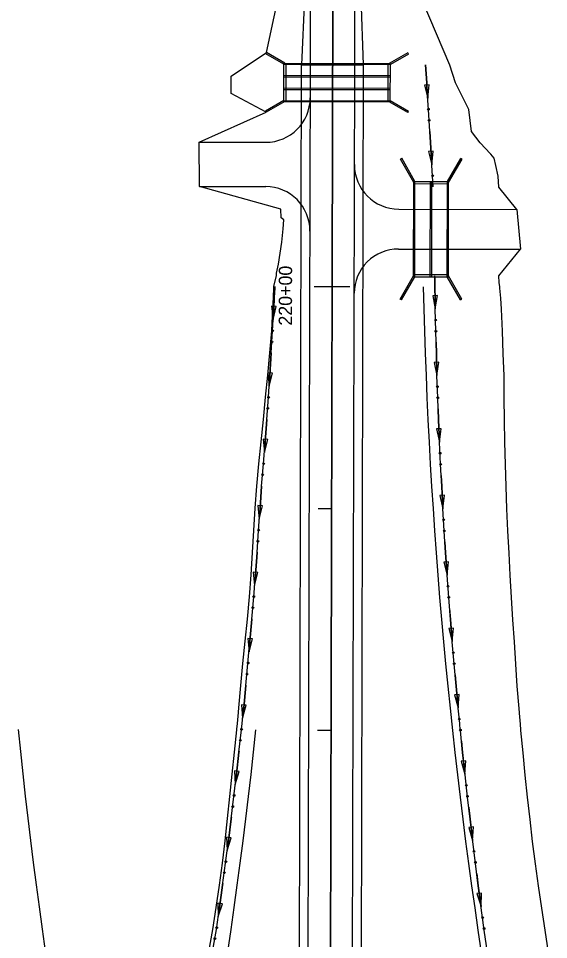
# Model space of a CAD drawing. Extents: x 1611108 to 1749517, y 619561 to 797725.
# Drawn here: x 1717474.1 to 1717713.2, y 766943.6 to 767358.9 of the extents above; entities that cross this region are included whole.
import ezdxf

# ---------------------------------------------------------------- set-up
doc = ezdxf.new("R2010")
doc.units = 0
for name, color, linetype in [('Level 8', 7, 'Continuous'), ('R_Ditch', 7, 'Continuous'), ('R_Drainage', 7, 'Continuous'), ('R_Horz Alg', 7, 'Continuous'), ('R_Horz Alg Stationing_Side Road', 7, 'Continuous'), ('R_Proposed Const Limits', 7, 'Continuous'), ('R_Proposed Road', 7, 'Continuous')]:
    doc.layers.add(name, color=color, linetype=linetype)

msp = doc.modelspace()

# ---------------------------------------------------------------- linework, layer by layer
at = {"layer": 'Level 8'}
msp.add_line((1717616.46, 767638.01), (1717610.87, 765238.01), dxfattribs=at)
at = {"layer": 'R_Ditch'}
for p, q in [((1717659.35, 767328.99), (1717657.24, 767328.86)), ((1717657.24, 767328.86), (1717658.67, 767322.94)), ((1717658.67, 767322.94), (1717659.35, 767328.99)), ((1717661.22, 767299.01), (1717659.11, 767298.88)), ((1717660.54, 767292.96), (1717661.22, 767299.01)), ((1717659.11, 767298.88), (1717660.54, 767292.96)), ((1717663.07, 767233.92), (1717660.95, 767233.88)), ((1717660.95, 767233.88), (1717662.12, 767227.9)), ((1717662.12, 767227.9), (1717663.07, 767233.92)), ((1717590.37, 767229.02), (1717588.26, 767229.13)), ((1717588.26, 767229.13), (1717589, 767223.09)), ((1717589, 767223.09), (1717590.37, 767229.02)), ((1717663.75, 767203.9), (1717661.64, 767203.84)), ((1717661.64, 767203.84), (1717662.87, 767197.87)), ((1717662.87, 767197.87), (1717663.75, 767203.9)), ((1717588.66, 767199.02), (1717586.55, 767199.16)), ((1717586.55, 767199.16), (1717587.21, 767193.1)), ((1717587.21, 767193.1), (1717588.66, 767199.02)), ((1717664.81, 767173.9), (1717662.7, 767173.81)), ((1717662.7, 767173.81), (1717664.01, 767167.86)), ((1717664.01, 767167.86), (1717664.81, 767173.9)), ((1717586.57, 767169.04), (1717584.46, 767169.21)), ((1717584.46, 767169.21), (1717585.05, 767163.14)), ((1717585.05, 767163.14), (1717586.57, 767169.04)), ((1717666.26, 767143.91), (1717664.15, 767143.79)), ((1717664.15, 767143.79), (1717665.54, 767137.86)), ((1717665.54, 767137.86), (1717666.26, 767143.91)), ((1717584.2, 767139.11), (1717582.09, 767139.25)), ((1717582.09, 767139.25), (1717582.76, 767133.19)), ((1717582.76, 767133.19), (1717584.2, 767139.11)), ((1717668.1, 767113.94), (1717665.99, 767113.8)), ((1717665.99, 767113.8), (1717667.45, 767107.88)), ((1717667.45, 767107.88), (1717668.1, 767113.94)), ((1717582.14, 767109.13), (1717580.03, 767109.29)), ((1717580.03, 767109.29), (1717580.62, 767103.23)), ((1717580.62, 767103.23), (1717582.14, 767109.13)), ((1717670.32, 767084), (1717668.21, 767083.83)), ((1717668.21, 767083.83), (1717669.75, 767077.93)), ((1717669.75, 767077.93), (1717670.32, 767084)), ((1717579.7, 767079.18), (1717577.59, 767079.37)), ((1717577.59, 767079.37), (1717578.11, 767073.3)), ((1717578.11, 767073.3), (1717579.7, 767079.18)), ((1717672.92, 767054.09), (1717670.82, 767053.89)), ((1717670.82, 767053.89), (1717672.43, 767048.01)), ((1717672.43, 767048.01), (1717672.92, 767054.09)), ((1717576.88, 767049.26), (1717574.77, 767049.48)), ((1717574.77, 767049.48), (1717575.21, 767043.4)), ((1717575.21, 767043.4), (1717576.88, 767049.26)), ((1717675.91, 767024.21), (1717673.8, 767023.99)), ((1717673.8, 767023.99), (1717675.49, 767018.13)), ((1717675.49, 767018.13), (1717675.91, 767024.21)), ((1717573.67, 767019.38), (1717571.57, 767019.63)), ((1717571.57, 767019.63), (1717571.93, 767013.54)), ((1717571.93, 767013.54), (1717573.67, 767019.38)), ((1717679.27, 766994.38), (1717677.17, 766994.12)), ((1717677.17, 766994.12), (1717678.93, 766988.29)), ((1717678.93, 766988.29), (1717679.27, 766994.38)), ((1717570.09, 766989.54), (1717567.99, 766989.82)), ((1717567.99, 766989.82), (1717568.27, 766983.73)), ((1717568.27, 766983.73), (1717570.09, 766989.54)), ((1717683.01, 766964.59), (1717680.91, 766964.31)), ((1717680.91, 766964.31), (1717682.75, 766958.5)), ((1717682.75, 766958.5), (1717683.01, 766964.59)), ((1717566.13, 766959.75), (1717564.03, 766960.05)), ((1717564.03, 766960.05), (1717564.23, 766953.96)), ((1717564.23, 766953.96), (1717566.13, 766959.75))]:
    msp.add_line(p, q, dxfattribs=at)
for points in [[(1717661.17, 767282.9), (1717660.85, 767287.9), (1717660.56, 767292.58), (1717660.36, 767295.9), (1717660.24, 767297.78), (1717660.23, 767297.9), (1717659.92, 767302.9), (1717659.61, 767307.91), (1717658.98, 767317.91), (1717658.36, 767327.91), (1717658.23, 767329.91), (1717657.73, 767337.91)], [(1717657.73, 767337.91), (1717658.23, 767329.91), (1717658.36, 767327.91), (1717658.67, 767322.94)], [(1717659.6, 767307.97), (1717659.6, 767307.93)], [(1717659.6, 767307.93), (1717659.61, 767307.91), (1717659.92, 767302.9), (1717660.23, 767297.9), (1717660.24, 767297.78), (1717660.36, 767295.9), (1717660.54, 767292.96)], [(1717685.62, 766937.84), (1717684.21, 766947.85), (1717682.84, 766957.85), (1717681.51, 766967.85), (1717680.23, 766977.86), (1717678.99, 766987.86), (1717677.79, 766997.86), (1717676.63, 767007.87), (1717675.52, 767017.87), (1717674.45, 767027.87), (1717673.43, 767037.87), (1717673.38, 767038.32), (1717673.15, 767040.69), (1717672.96, 767042.61), (1717672.83, 767043.88), (1717672.44, 767047.88), (1717672.44, 767047.91), (1717671.5, 767057.88), (1717670.61, 767067.88), (1717669.75, 767077.88), (1717668.94, 767087.88), (1717668.18, 767097.89), (1717667.45, 767107.89), (1717666.77, 767117.89), (1717666.13, 767127.89), (1717665.54, 767137.89), (1717664.99, 767147.89), (1717664.48, 767157.89), (1717664.01, 767167.9), (1717663.59, 767177.9), (1717663.21, 767187.9), (1717662.87, 767197.9), (1717662.58, 767207.9), (1717662.33, 767217.9), (1717662.12, 767227.9), (1717662.03, 767232.84), (1717661.96, 767237.3), (1717661.95, 767237.9), (1717661.92, 767239.94), (1717661.89, 767242.9)], [(1717661.89, 767242.4), (1717661.92, 767239.94), (1717661.95, 767237.9), (1717661.96, 767237.3), (1717662.03, 767232.84), (1717662.12, 767227.9)], [(1717561.58, 766938.13), (1717563.4, 766948.13), (1717564.83, 766958.13), (1717566.21, 766968.12), (1717567.54, 766978.12), (1717568.84, 766988.12), (1717570.09, 766998.11), (1717571.29, 767008.11), (1717572.46, 767018.11), (1717573.58, 767028.11), (1717574.66, 767038.1), (1717574.71, 767038.55), (1717574.95, 767040.92), (1717575.15, 767042.84), (1717575.29, 767044.11), (1717575.69, 767048.1), (1717575.7, 767048.13), (1717576.69, 767058.1), (1717577.63, 767068.1), (1717578.54, 767078.09), (1717579.4, 767088.09), (1717580.22, 767098.09), (1717581, 767108.09), (1717581.74, 767118.09), (1717582.43, 767128.08), (1717583.07, 767138.08), (1717583.81, 767148.08), (1717584.65, 767158.08), (1717585.43, 767168.08), (1717586.18, 767178.08), (1717586.88, 767188.07), (1717587.54, 767198.07), (1717588.16, 767208.07), (1717588.73, 767218.07), (1717589.26, 767228.07), (1717589.51, 767233.01), (1717589.72, 767237.47), (1717589.75, 767238.07)], [(1717589.75, 767238.07), (1717589.72, 767237.47), (1717589.51, 767233.01), (1717589.26, 767228.07), (1717589, 767223.09)], [(1717683.01, 766937.85), (1717681.51, 766947.85), (1717680.06, 766957.86), (1717678.64, 766967.86), (1717677.28, 766977.86), (1717675.95, 766987.87), (1717674.67, 766997.87), (1717673.43, 767007.87), (1717672.23, 767017.88), (1717671.08, 767027.88), (1717669.97, 767037.88), (1717668.9, 767047.88), (1717667.88, 767057.89), (1717666.9, 767067.89), (1717665.96, 767077.89), (1717665.07, 767087.89), (1717664.21, 767097.89), (1717663.41, 767107.9), (1717662.64, 767117.9), (1717661.92, 767127.9), (1717661.24, 767137.9), (1717660.6, 767147.9), (1717660.01, 767157.9), (1717659.46, 767167.91), (1717658.95, 767177.91), (1717658.49, 767187.91), (1717658.07, 767197.91), (1717657.69, 767207.91), (1717657.35, 767217.91), (1717657.06, 767227.91), (1717656.81, 767237.91)], [(1717662.45, 767212.91), (1717662.45, 767212.87)], [(1717662.45, 767212.87), (1717662.58, 767207.9), (1717662.87, 767197.9), (1717662.87, 767197.87)], [(1717588.16, 767208.07), (1717588.16, 767208.07), (1717587.54, 767198.07), (1717587.21, 767193.1)], [(1717588.16, 767208.11), (1717588.16, 767208.07)], [(1717663.4, 767182.88), (1717663.4, 767182.85)], [(1717663.4, 767182.84), (1717663.59, 767177.9), (1717664.01, 767167.9), (1717664.01, 767167.86)], [(1717586.18, 767178.1), (1717586.18, 767178.08), (1717585.43, 767168.08), (1717585.05, 767163.14)], [(1717586.18, 767178.14), (1717586.18, 767178.1)], [(1717664.73, 767152.87), (1717664.73, 767152.84)], [(1717664.73, 767152.84), (1717664.99, 767147.89), (1717665.54, 767137.89), (1717665.54, 767137.86)], [(1717583.82, 767148.15), (1717583.81, 767148.08), (1717583.07, 767138.08), (1717582.76, 767133.19)], [(1717583.82, 767148.19), (1717583.82, 767148.16)], [(1717666.45, 767122.89), (1717666.45, 767122.85)], [(1717666.45, 767122.85), (1717666.77, 767117.89), (1717667.45, 767107.89), (1717667.45, 767107.88)], [(1717581.74, 767118.19), (1717581.74, 767118.09), (1717581, 767108.09), (1717580.62, 767103.23)], [(1717581.74, 767118.23), (1717581.74, 767118.19)], [(1717668.56, 767092.92), (1717668.56, 767092.89)], [(1717668.56, 767092.88), (1717668.94, 767087.88), (1717669.75, 767077.93)], [(1717579.42, 767088.24), (1717579.4, 767088.09), (1717578.54, 767078.09), (1717578.11, 767073.3)], [(1717579.42, 767088.28), (1717579.42, 767088.24)], [(1717671.05, 767062.99), (1717671.05, 767062.95)], [(1717671.05, 767062.95), (1717671.5, 767057.88), (1717672.43, 767048.01)], [(1717576.71, 767058.33), (1717576.69, 767058.1), (1717575.7, 767048.13), (1717575.69, 767048.1), (1717575.29, 767044.11), (1717575.21, 767043.4)], [(1717576.71, 767058.36), (1717576.71, 767058.33)], [(1717486.38, 766938.31), (1717484.96, 766948.31), (1717483.59, 766958.31), (1717482.26, 766968.32), (1717480.96, 766978.32), (1717479.72, 766988.32), (1717478.51, 766998.33), (1717477.35, 767008.33), (1717476.23, 767018.33), (1717475.16, 767028.33), (1717474.13, 767038.34)], [(1717568.53, 766938.12), (1717569.99, 766948.11), (1717571.41, 766958.11), (1717572.79, 766968.11), (1717574.13, 766978.1), (1717575.42, 766988.1), (1717576.67, 766998.1), (1717577.88, 767008.1), (1717579.05, 767018.09), (1717580.17, 767028.09), (1717581.25, 767038.09)], [(1717673.92, 767033.09), (1717673.92, 767033.05)], [(1717673.92, 767033.05), (1717674.45, 767027.87), (1717675.49, 767018.13)], [(1717573.62, 767028.45), (1717573.58, 767028.11), (1717572.46, 767018.11), (1717571.93, 767013.54)], [(1717573.62, 767028.49), (1717573.62, 767028.45)], [(1717677.17, 767003.23), (1717677.17, 767003.19)], [(1717677.17, 767003.19), (1717677.79, 766997.86), (1717678.93, 766988.29)], [(1717570.15, 766998.61), (1717570.09, 766998.11), (1717568.84, 766988.12), (1717568.27, 766983.73)], [(1717570.15, 766998.65), (1717570.15, 766998.61)], [(1717680.8, 766973.41), (1717680.8, 766973.37)], [(1717680.8, 766973.37), (1717681.51, 766967.85), (1717682.75, 766958.5)], [(1717566.3, 766968.82), (1717566.21, 766968.12), (1717564.83, 766958.13), (1717564.23, 766953.96)], [(1717566.3, 766968.86), (1717566.3, 766968.82)], [(1717684.8, 766943.64), (1717684.81, 766943.6)]]:
    msp.add_lwpolyline(points, dxfattribs=at)
for centre in [(1717659.02, 767317.95), (1717659.33, 767312.94), (1717660.89, 767287.97), (1717662.26, 767222.9), (1717588.77, 767218.09), (1717662.36, 767217.89), (1717588.48, 767213.08), (1717663.08, 767192.87), (1717586.92, 767188.1), (1717663.24, 767187.86), (1717586.57, 767183.11), (1717664.28, 767162.86), (1717584.69, 767158.15), (1717664.51, 767157.85), (1717584.27, 767153.16), (1717665.87, 767132.86), (1717582.47, 767128.19), (1717666.17, 767127.86), (1717582.12, 767123.2), (1717667.85, 767102.89), (1717580.27, 767098.24), (1717668.21, 767097.89), (1717579.86, 767093.24), (1717670.21, 767072.95), (1717577.69, 767068.31), (1717670.64, 767067.96), (1717577.22, 767063.32), (1717672.95, 767043.03), (1717574.73, 767038.42), (1717673.45, 767038.05), (1717574.19, 767033.44), (1717676.08, 767013.16), (1717571.38, 767008.57), (1717676.63, 767008.18), (1717570.78, 767003.59), (1717679.58, 766983.33), (1717567.66, 766978.76), (1717680.2, 766978.36), (1717567, 766973.79), (1717683.46, 766953.54), (1717563.56, 766949), (1717684.14, 766948.58), (1717562.7, 766944.07)]:
    msp.add_circle(centre, 0.375, dxfattribs=at)
at = {"layer": 'R_Drainage'}
for p, q in [((1717585.63, 767342.99), (1717585.97, 767343.57)), ((1717593.85, 767338.23), (1717585.63, 767342.99)), ((1717594.32, 767338.72), (1717585.97, 767343.57)), ((1717649.75, 767343.42), (1717641.38, 767338.61)), ((1717650.09, 767342.84), (1717641.85, 767338.11)), ((1717650.09, 767342.84), (1717649.75, 767343.42)), ((1717593.81, 767321.39), (1717593.85, 767338.73)), ((1717593.85, 767338.73), (1717641.85, 767338.61)), ((1717593.85, 767338.23), (1717641.85, 767338.11)), ((1717594.81, 767321.39), (1717594.85, 767338.72)), ((1717640.81, 767321.28), (1717640.85, 767338.62)), ((1717641.81, 767321.28), (1717641.85, 767338.61)), ((1717593.84, 767333.23), (1717641.84, 767333.11)), ((1717593.84, 767332.56), (1717641.84, 767332.45)), ((1717593.82, 767327.56), (1717641.82, 767327.45)), ((1717593.82, 767326.89), (1717641.82, 767326.78)), ((1717593.81, 767321.89), (1717585.57, 767317.16)), ((1717594.28, 767321.39), (1717585.9, 767316.58)), ((1717593.81, 767321.89), (1717641.81, 767321.78)), ((1717593.81, 767321.39), (1717641.81, 767321.28)), ((1717649.69, 767316.43), (1717641.34, 767321.28)), ((1717650.03, 767317.01), (1717641.81, 767321.78)), ((1717585.9, 767316.58), (1717585.57, 767317.16)), ((1717649.69, 767316.43), (1717650.03, 767317.01)), ((1717646.37, 767295.5), (1717646.95, 767295.83)), ((1717652.42, 767284.96), (1717646.37, 767295.5)), ((1717652.92, 767285.42), (1717646.95, 767295.83)), ((1717667.59, 767285.39), (1717673.61, 767295.77)), ((1717668.09, 767284.92), (1717674.19, 767295.43)), ((1717674.19, 767295.43), (1717673.61, 767295.77)), ((1717652.32, 767242.42), (1717652.42, 767285.42)), ((1717652.42, 767285.42), (1717668.09, 767285.39)), ((1717652.42, 767284.42), (1717668.09, 767284.39)), ((1717652.82, 767242.42), (1717652.92, 767285.42)), ((1717659.82, 767242.4), (1717659.92, 767285.4)), ((1717660.49, 767242.4), (1717660.59, 767285.4)), ((1717667.49, 767242.39), (1717667.59, 767285.39)), ((1717667.99, 767242.39), (1717668.09, 767285.39)), ((1717646.22, 767232.38), (1717652.32, 767242.89)), ((1717646.8, 767232.04), (1717652.82, 767242.42)), ((1717652.32, 767243.42), (1717667.99, 767243.39)), ((1717652.32, 767242.42), (1717667.99, 767242.39)), ((1717673.46, 767231.98), (1717667.49, 767242.39)), ((1717674.04, 767232.31), (1717667.99, 767242.85)), ((1717646.8, 767232.04), (1717646.22, 767232.38)), ((1717673.46, 767231.98), (1717674.04, 767232.31))]:
    msp.add_line(p, q, dxfattribs=at)
at = {"layer": 'R_Horz Alg'}
msp.add_line((1717610.87, 765238.01), (1717616.46, 767638.01), dxfattribs=at)
at = {"layer": 'R_Horz Alg Stationing_Side Road'}
for points in [[(1717609.76, 767338.02), (1717615.76, 767338.01)], [(1717607.53, 767238.03), (1717623.53, 767237.99)], [(1717609.29, 767138.02), (1717615.29, 767138.01)], [(1717609.06, 767038.02), (1717615.06, 767038.01)]]:
    msp.add_lwpolyline(points, dxfattribs=at)
at = {"layer": 'R_Proposed Const Limits'}
for points in [[(1717555.68, 767303.14), (1717585.9, 767316.58), (1717570.06, 767325.08), (1717570.08, 767332.85), (1717585.97, 767343.57), (1717606.23, 767438.03)], [(1717698.9, 767272.81), (1717690.79, 767282.83), (1717690.45, 767287.83), (1717689.4, 767292.52), (1717688.58, 767295.84), (1717687.18, 767297.72), (1717687.06, 767297.84), (1717682.37, 767302.85), (1717678.39, 767307.86), (1717677.21, 767317.86), (1717671.21, 767329.88), (1717668.62, 767337.88), (1717626.08, 767437.98)], [(1717593.87, 767268.06), (1717592.65, 767268.95), (1717592.41, 767272.91), (1717555.75, 767283.14)], [(1717589.31, 767238.07), (1717590.47, 767243.07), (1717590.57, 767244.07), (1717591.43, 767248.06), (1717592.88, 767258.06), (1717593.58, 767264.06), (1717593.87, 767268.06)], [(1717713.19, 766937.78), (1717711.68, 766947.78), (1717710.19, 766957.79), (1717708.72, 766967.79), (1717707.23, 766977.79), (1717705.99, 766987.8), (1717704.84, 766997.8), (1717703.74, 767007.8), (1717702.7, 767017.8), (1717701.68, 767027.81), (1717700.72, 767037.81), (1717700.68, 767038.26), (1717700.47, 767040.62), (1717700.31, 767042.55), (1717700.2, 767043.82), (1717699.86, 767047.81), (1717699.86, 767047.84), (1717699.07, 767057.81), (1717698.47, 767067.81), (1717697.78, 767077.82), (1717697.12, 767087.82), (1717696.5, 767097.82), (1717695.92, 767107.82), (1717695.36, 767117.82), (1717694.84, 767127.82), (1717694.4, 767137.82), (1717694.06, 767147.83), (1717693.81, 767157.83), (1717693.47, 767167.83), (1717693.31, 767177.83), (1717693.11, 767187.83), (1717693.14, 767197.83), (1717692.67, 767207.83), (1717692.38, 767217.83), (1717691.9, 767227.83), (1717691.68, 767232.77), (1717691.23, 767237.23), (1717691.15, 767237.83), (1717690.9, 767239.88), (1717690.69, 767242.83), (1717700.58, 767254.81)], [(1717559.96, 766938.14), (1717561.85, 766948.13), (1717563.31, 766958.13), (1717564.73, 766968.13), (1717566.13, 766978.12), (1717567.36, 766988.12), (1717568.44, 766998.12), (1717569.51, 767008.11), (1717570.53, 767018.11), (1717571.49, 767028.11), (1717572.62, 767038.11), (1717572.66, 767038.55), (1717572.88, 767040.92), (1717573.06, 767042.84), (1717573.18, 767044.11), (1717573.54, 767048.11), (1717573.55, 767048.14), (1717574.43, 767058.1), (1717575.33, 767068.1), (1717576.38, 767078.1), (1717577.36, 767088.1), (1717578.29, 767098.09), (1717579.1, 767108.09), (1717579.72, 767118.09), (1717580.3, 767128.09), (1717580.87, 767138.09), (1717581.61, 767148.09), (1717582.6, 767158.08), (1717583.56, 767168.08), (1717584.6, 767178.08), (1717585.61, 767188.08), (1717586.57, 767198.08), (1717587.47, 767208.07), (1717588.34, 767218.07), (1717588.9, 767228.07), (1717589.11, 767233.01), (1717589.29, 767237.47), (1717589.31, 767238.07)]]:
    msp.add_lwpolyline(points, dxfattribs=at)
at = {"layer": 'R_Proposed Road'}
for p, q in [((1717606.23, 767438.03), (1717601.76, 767338.04)), ((1717605.76, 767338.03), (1717606.23, 767438.03)), ((1717625.76, 767337.98), (1717626.08, 767437.98)), ((1717629.76, 767337.98), (1717626.08, 767437.98)), ((1717597.57, 765538.05), (1717601.76, 767338.04)), ((1717601.57, 765538.04), (1717605.76, 767338.03)), ((1717601.76, 767338.04), (1717629.76, 767337.98)), ((1717621.57, 765537.99), (1717625.76, 767337.98)), ((1717625.57, 765537.98), (1717629.76, 767337.98)), ((1717555.68, 767303.14), (1717585.68, 767303.08)), ((1717555.75, 767283.14), (1717585.63, 767283.08)), ((1717645.61, 767272.94), (1717698.9, 767272.81)), ((1717698.9, 767272.81), (1717700.58, 767254.81)), ((1717645.56, 767254.94), (1717700.58, 767254.81))]:
    msp.add_line(p, q, dxfattribs=at)
msp.add_lwpolyline([(1717555.75, 767283.14), (1717555.68, 767303.14)], dxfattribs=at)
for centre, start, end in [((1717585.72, 767323.08), 269.8667, 359.8667), ((1717645.65, 767292.94), 179.8667, 269.8667), ((1717585.58, 767263.08), 359.8667, 89.8667), ((1717645.52, 767234.94), 89.8667, 179.8667)]:
    msp.add_arc(centre, 20, start, end, dxfattribs=at)

# ---------------------------------------------------------------- texts
at = {"layer": 'R_Horz Alg Stationing_Side Road'}
msp.add_text('220+00', height=6, rotation=89.8667, dxfattribs=at).set_placement((1717597.48, 767220.4))

doc.saveas('drawing.dxf')
